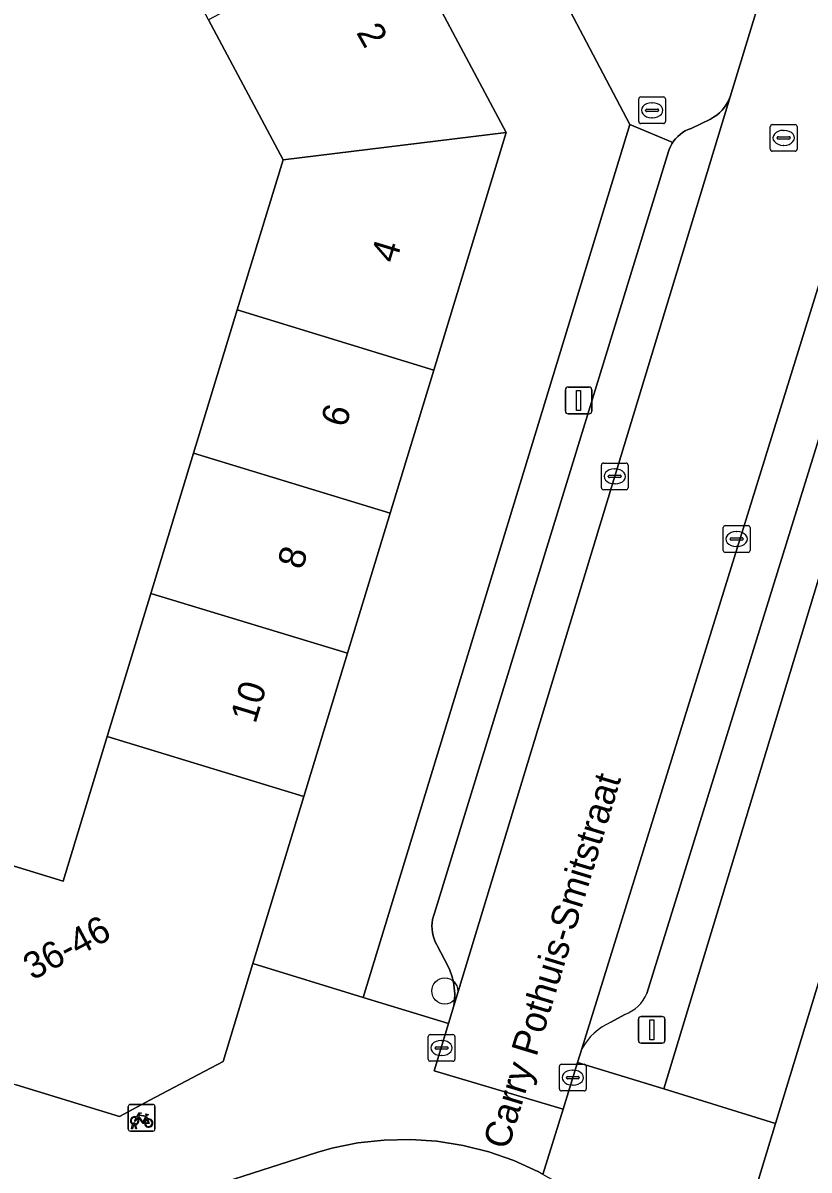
# Model space of a CAD drawing. Extents: x 160304 to 160955, y 383684 to 384161.
# Drawn here: x 160683.55 to 160713, y 383795.43 to 383838.38 of the extents above; entities that cross this region are included whole.
import ezdxf

# ---------------------------------------------------------------- set-up
doc = ezdxf.new("R2010")
doc.units = 0
for name, color, linetype in [('IMGEO_Boom', 7, 'Continuous'), ('IMGEO_Brandkraan', 7, 'Continuous'), ('IMGEO_Erf', 7, 'Continuous'), ('IMGEO_Fietsenrek', 7, 'Continuous'), ('IMGEO_Kolk', 7, 'Continuous'), ('IMGEO_Lichtmast', 7, 'Continuous'), ('IMGEO_Openbare_ruimte_label', 7, 'Continuous'), ('IMGEO_Pand', 7, 'Continuous'), ('IMGEO_Pand_nummerreeks', 7, 'Continuous'), ('IMGEO_Parkeervlak_open', 7, 'Continuous'), ('IMGEO_Rijbaan_lokaal_open', 7, 'Continuous'), ('IMGEO_Rioolput', 7, 'Continuous'), ('IMGEO_Voetpad_open', 7, 'Continuous')]:
    doc.layers.add(name, color=color, linetype=linetype)

msp = doc.modelspace()

# ---------------------------------------------------------------- linework, layer by layer
at = {"layer": 'IMGEO_Boom'}
msp.add_circle((160699.356, 383802.137), 0.489, dxfattribs=at)
at = {"layer": 'IMGEO_Brandkraan'}
for p, q in [((160706.695, 383835.615), (160707.547, 383835.615)), ((160706.62, 383834.689), (160706.62, 383835.541)), ((160707.108, 383835.395), (160707.133, 383835.395)), ((160707.621, 383835.541), (160707.621, 383834.689)), ((160706.879, 383835.109), (160706.879, 383835.121)), ((160707.317, 383835.072), (160706.919, 383835.072)), ((160706.922, 383835.158), (160707.32, 383835.158)), ((160707.131, 383834.835), (160707.106, 383834.835)), ((160707.363, 383835.121), (160707.363, 383835.109)), ((160707.547, 383834.615), (160706.695, 383834.615))]:
    msp.add_line(p, q, dxfattribs=at)
for points in [[(160706.695, 383835.615), (160707.547, 383835.615)], [(160706.62, 383834.689), (160706.62, 383835.541)], [(160707.621, 383835.541), (160707.621, 383834.689)], [(160707.547, 383834.615), (160706.695, 383834.615)]]:
    msp.add_lwpolyline(points, dxfattribs=at)
for centre, radius, start, end in [((160706.697, 383835.539), 0.0765, 91.552, 178.448), ((160706.697, 383835.539), 0.0765, 91.552, 178.448), ((160707.545, 383835.539), 0.0765, 1.552, 88.448), ((160707.545, 383835.539), 0.0765, 1.552, 88.448), ((160706.919, 383835.118), 0.0403, 85.8775, 175.7526), ((160706.916, 383835.108), 0.0366, 178.938, 274.7102), ((160707.32, 383835.115), 0.043, 264.8664, 352.4533), ((160707.324, 383835.12), 0.0386, 1.7309, 96.639), ((160706.697, 383834.691), 0.0765, 181.552, 268.448), ((160706.697, 383834.691), 0.0765, 181.552, 268.448), ((160707.545, 383834.691), 0.0765, 271.552, 358.448), ((160707.545, 383834.691), 0.0765, 271.552, 358.448)]:
    msp.add_arc(centre, radius, start, end, dxfattribs=at)
for centre, major_axis, ratio, start_param, end_param in [((160707.107, 383835.115), (-0.387, 0.002), 0.722429, 4.712389, 7.853982), ((160707.132, 383835.115), (-0.39, 0.002), 0.717154, 1.570796, 4.712389)]:
    msp.add_ellipse(centre, major_axis=major_axis, ratio=ratio, start_param=start_param, end_param=end_param, dxfattribs=at)
at = {"layer": 'IMGEO_Erf'}
for points in [[(160706.29, 383834.575), (160698.822, 383848.768), (160696.833, 383850.07), (160689.542, 383863.958), (160687.096, 383862.66), (160686.663, 383862.43), (160689.481, 383857.138), (160692.156, 383852.115), (160694.833, 383847.089), (160697.446, 383842.182), (160701.657, 383834.275), (160698.945, 383825.386), (160697.309, 383820.026), (160695.709, 383814.78), (160694.073, 383809.418), (160692.164, 383803.164), (160696.3, 383801.889)], [(160734.168, 383835.135), (160739.273, 383837.851), (160744.418, 383840.589), (160742.884, 383843.475), (160733.308, 383838.386), (160731.697, 383838.95), (160717.579, 383831.466), (160707.563, 383798.475), (160711.75, 383797.173), (160714.27, 383805.428), (160715.618, 383809.843), (160716.966, 383814.258), (160718.314, 383818.674), (160721.24, 383828.255), (160729.062, 383832.418)]]:
    msp.add_lwpolyline(points, close=True, dxfattribs=at)
msp.add_lwpolyline([(160679.665, 383807.898), (160685.059, 383806.252), (160686.712, 383811.669), (160688.346, 383817.026), (160689.947, 383822.272), (160691.583, 383827.636), (160693.298, 383833.257), (160690.506, 383838.5), (160687.891, 383843.41), (160685.222, 383848.423), (160682.541, 383853.456)], dxfattribs=at)
at = {"layer": 'IMGEO_Fietsenrek'}
for p, q in [((160687.571, 383797.891), (160688.412, 383797.891)), ((160688.412, 383797.891), (160687.571, 383797.891)), ((160688.496, 383797.816), (160688.496, 383796.975)), ((160688.496, 383796.975), (160688.496, 383797.816)), ((160687.496, 383796.966), (160687.496, 383797.807)), ((160687.496, 383797.807), (160687.496, 383796.966)), ((160688.183, 383797.44), (160688.219, 383797.345)), ((160687.623, 383796.975), (160687.662, 383797.135)), ((160687.657, 383796.975), (160687.623, 383796.975)), ((160687.692, 383797.123), (160687.657, 383796.975)), ((160687.734, 383797.147), (160687.733, 383797.151)), ((160687.775, 383796.975), (160687.741, 383797.117)), ((160687.765, 383797.158), (160687.766, 383797.151)), ((160687.773, 383797.121), (160687.808, 383796.975)), ((160687.808, 383796.975), (160687.775, 383796.975)), ((160688.421, 383796.891), (160687.58, 383796.891)), ((160687.58, 383796.891), (160688.421, 383796.891))]:
    msp.add_line(p, q, dxfattribs=at)
for points in [[(160687.83, 383797.365), (160687.778, 383797.275), (160687.738, 383797.25), (160687.739, 383797.297), (160687.794, 383797.391)], [(160687.809, 383797.417), (160687.904, 383797.581), (160687.99, 383797.567), (160687.992, 383797.558), (160687.936, 383797.547), (160687.909, 383797.502), (160688.165, 383797.461)], [(160688.105, 383797.173), (160688.055, 383797.173), (160687.864, 383797.424), (160687.845, 383797.392)], [(160688.152, 383797.436), (160687.895, 383797.477), (160687.878, 383797.448), (160688.045, 383797.228), (160688.152, 383797.436)], [(160688.2, 383797.338), (160688.17, 383797.415), (160688.061, 383797.197), (160688.104, 383797.197)], [(160688.165, 383797.461), (160688.19, 383797.51), (160688.184, 383797.514), (160688.161, 383797.518), (160688.149, 383797.525), (160688.148, 383797.528), (160688.15, 383797.533), (160688.245, 383797.518), (160688.247, 383797.508), (160688.237, 383797.495), (160688.225, 383797.489), (160688.211, 383797.495), (160688.183, 383797.44)], [(160688.134, 383797.197), (160688.254, 383797.196), (160688.21, 383797.31)], [(160688.23, 383797.317), (160688.285, 383797.172), (160688.135, 383797.172)]]:
    msp.add_lwpolyline(points, dxfattribs=at)
for centre, radius, start, end in [((160687.574, 383797.813), 0.0779, 92.4484, 184.2845), ((160687.574, 383797.813), 0.0779, 92.4484, 184.2845), ((160688.418, 383797.813), 0.0779, 2.4484, 94.2845), ((160688.418, 383797.813), 0.0779, 2.4484, 94.2845), ((160687.736, 383797.276), 0.159, 62.6766, 242.1369), ((160687.736, 383797.276), 0.129, 63.3192, 238.903), ((160687.736, 383797.276), 0.159, 283.5766, 46.6042), ((160687.574, 383796.969), 0.0779, 182.4484, 274.2845), ((160687.574, 383796.969), 0.0779, 182.4484, 274.2845), ((160687.716, 383797.147), 0.0499, 12.8025, 158.6934), ((160687.736, 383797.276), 0.159, 253.9967, 271.7867), ((160687.716, 383797.147), 0.0174, 12.8025, 163.4502), ((160687.736, 383797.276), 0.129, 253.415, 269.0204), ((160687.736, 383797.276), 0.129, 283.6043, 43.4302), ((160688.263, 383797.192), 0.159, 113.3408, 178.3217), ((160688.263, 383797.192), 0.159, 187.0065, 105.7708), ((160688.263, 383797.192), 0.129, 113.923, 177.9556), ((160688.263, 383797.192), 0.129, 188.6715, 104.5883), ((160688.418, 383796.969), 0.0779, 272.4484, 4.2845), ((160688.418, 383796.969), 0.0779, 272.4484, 4.2845)]:
    msp.add_arc(centre, radius, start, end, dxfattribs=at)
at = {"layer": 'IMGEO_Kolk'}
for p, q in [((160705.297, 383821.905), (160706.149, 383821.905)), ((160705.222, 383820.979), (160705.222, 383821.831)), ((160705.524, 383821.448), (160705.922, 383821.448)), ((160705.71, 383821.685), (160705.735, 383821.685)), ((160706.223, 383821.831), (160706.223, 383820.979)), ((160705.481, 383821.399), (160705.481, 383821.411)), ((160705.919, 383821.362), (160705.521, 383821.362)), ((160705.733, 383821.125), (160705.708, 383821.125)), ((160705.965, 383821.411), (160705.965, 383821.399)), ((160706.149, 383820.905), (160705.297, 383820.905)), ((160709.788, 383818.634), (160709.788, 383819.486)), ((160709.863, 383819.56), (160710.715, 383819.56)), ((160710.276, 383819.34), (160710.301, 383819.34)), ((160710.789, 383819.486), (160710.789, 383818.634)), ((160710.047, 383819.054), (160710.047, 383819.066)), ((160710.485, 383819.017), (160710.087, 383819.017)), ((160710.09, 383819.103), (160710.488, 383819.103)), ((160710.531, 383819.066), (160710.531, 383819.054)), ((160710.715, 383818.56), (160709.863, 383818.56)), ((160710.299, 383818.78), (160710.274, 383818.78)), ((160698.733, 383799.578), (160698.733, 383800.43)), ((160698.808, 383800.504), (160699.66, 383800.504)), ((160699.734, 383800.43), (160699.734, 383799.578)), ((160698.992, 383799.998), (160698.992, 383800.01)), ((160699.43, 383799.961), (160699.032, 383799.961)), ((160699.035, 383800.047), (160699.433, 383800.047)), ((160699.221, 383800.284), (160699.246, 383800.284)), ((160699.476, 383800.01), (160699.476, 383799.998)), ((160699.244, 383799.724), (160699.219, 383799.724)), ((160699.66, 383799.504), (160698.808, 383799.504)), ((160703.65, 383798.467), (160703.65, 383799.319)), ((160703.725, 383799.393), (160704.577, 383799.393)), ((160704.138, 383799.173), (160704.163, 383799.173)), ((160704.651, 383799.319), (160704.651, 383798.467)), ((160703.909, 383798.887), (160703.909, 383798.899)), ((160704.347, 383798.85), (160703.949, 383798.85)), ((160703.952, 383798.936), (160704.35, 383798.936)), ((160704.393, 383798.899), (160704.393, 383798.887)), ((160704.577, 383798.393), (160703.725, 383798.393)), ((160704.161, 383798.613), (160704.136, 383798.613))]:
    msp.add_line(p, q, dxfattribs=at)
for points in [[(160705.297, 383821.905), (160706.149, 383821.905)], [(160705.222, 383820.979), (160705.222, 383821.831)], [(160706.223, 383821.831), (160706.223, 383820.979)], [(160706.149, 383820.905), (160705.297, 383820.905)], [(160709.788, 383818.634), (160709.788, 383819.486)], [(160709.863, 383819.56), (160710.715, 383819.56)], [(160710.789, 383819.486), (160710.789, 383818.634)], [(160710.715, 383818.56), (160709.863, 383818.56)], [(160698.733, 383799.578), (160698.733, 383800.43)], [(160698.808, 383800.504), (160699.66, 383800.504)], [(160699.734, 383800.43), (160699.734, 383799.578)], [(160699.66, 383799.504), (160698.808, 383799.504)], [(160703.65, 383798.467), (160703.65, 383799.319)], [(160703.725, 383799.393), (160704.577, 383799.393)], [(160704.651, 383799.319), (160704.651, 383798.467)], [(160704.577, 383798.393), (160703.725, 383798.393)]]:
    msp.add_lwpolyline(points, dxfattribs=at)
for centre, radius, start, end in [((160705.299, 383821.829), 0.0765, 91.552, 178.448), ((160705.299, 383821.829), 0.0765, 91.552, 178.448), ((160706.147, 383821.829), 0.0765, 1.552, 88.448), ((160706.147, 383821.829), 0.0765, 1.552, 88.448), ((160705.521, 383821.408), 0.0403, 85.8775, 175.7526), ((160705.926, 383821.41), 0.0386, 1.7309, 96.639), ((160705.518, 383821.398), 0.0366, 178.938, 274.7102), ((160705.922, 383821.405), 0.043, 264.8664, 352.4533), ((160705.299, 383820.981), 0.0765, 181.552, 268.448), ((160705.299, 383820.981), 0.0765, 181.552, 268.448), ((160706.147, 383820.981), 0.0765, 271.552, 358.448), ((160706.147, 383820.981), 0.0765, 271.552, 358.448), ((160709.865, 383819.484), 0.0765, 91.552, 178.448), ((160709.865, 383819.484), 0.0765, 91.552, 178.448), ((160710.713, 383819.484), 0.0765, 1.552, 88.448), ((160710.713, 383819.484), 0.0765, 1.552, 88.448), ((160710.087, 383819.063), 0.0403, 85.8775, 175.7526), ((160710.084, 383819.053), 0.0366, 178.938, 274.7102), ((160710.488, 383819.06), 0.043, 264.8664, 352.4533), ((160710.492, 383819.065), 0.0386, 1.7309, 96.639), ((160709.865, 383818.636), 0.0765, 181.552, 268.448), ((160709.865, 383818.636), 0.0765, 181.552, 268.448), ((160710.713, 383818.636), 0.0765, 271.552, 358.448), ((160710.713, 383818.636), 0.0765, 271.552, 358.448), ((160698.81, 383800.428), 0.0765, 91.552, 178.448), ((160698.81, 383800.428), 0.0765, 91.552, 178.448), ((160699.658, 383800.428), 0.0765, 1.552, 88.448), ((160699.658, 383800.428), 0.0765, 1.552, 88.448), ((160699.032, 383800.007), 0.0403, 85.8775, 175.7526), ((160699.029, 383799.997), 0.0366, 178.938, 274.7102), ((160699.433, 383800.004), 0.043, 264.8664, 352.4533), ((160699.437, 383800.009), 0.0386, 1.7309, 96.639), ((160698.81, 383799.58), 0.0765, 181.552, 268.448), ((160698.81, 383799.58), 0.0765, 181.552, 268.448), ((160699.658, 383799.58), 0.0765, 271.552, 358.448), ((160699.658, 383799.58), 0.0765, 271.552, 358.448), ((160703.727, 383799.317), 0.0765, 91.552, 178.448), ((160703.727, 383799.317), 0.0765, 91.552, 178.448), ((160704.575, 383799.317), 0.0765, 1.552, 88.448), ((160704.575, 383799.317), 0.0765, 1.552, 88.448), ((160703.949, 383798.896), 0.0403, 85.8775, 175.7526), ((160703.946, 383798.886), 0.0366, 178.938, 274.7102), ((160704.35, 383798.893), 0.043, 264.8664, 352.4533), ((160704.354, 383798.898), 0.0386, 1.7309, 96.639), ((160703.727, 383798.469), 0.0765, 181.552, 268.448), ((160703.727, 383798.469), 0.0765, 181.552, 268.448), ((160704.575, 383798.469), 0.0765, 271.552, 358.448), ((160704.575, 383798.469), 0.0765, 271.552, 358.448)]:
    msp.add_arc(centre, radius, start, end, dxfattribs=at)
for centre, major_axis, ratio, start_param, end_param in [((160705.709, 383821.405), (-0.387, 0.002), 0.722429, 4.712389, 7.853982), ((160705.734, 383821.405), (-0.39, 0.002), 0.717154, 1.570796, 4.712389), ((160710.275, 383819.06), (-0.387, 0.002), 0.722429, 4.712389, 7.853982), ((160710.3, 383819.06), (-0.39, 0.002), 0.717154, 1.570796, 4.712389), ((160699.22, 383800.004), (-0.387, 0.002), 0.722429, 4.712389, 7.853982), ((160699.245, 383800.004), (-0.39, 0.002), 0.717154, 1.570796, 4.712389), ((160704.137, 383798.893), (-0.387, 0.002), 0.722429, 4.712389, 7.853982), ((160704.162, 383798.893), (-0.39, 0.002), 0.717154, 1.570796, 4.712389)]:
    msp.add_ellipse(centre, major_axis=major_axis, ratio=ratio, start_param=start_param, end_param=end_param, dxfattribs=at)
at = {"layer": 'IMGEO_Lichtmast'}
for p, q in [((160703.875, 383823.849), (160703.875, 383824.649)), ((160703.875, 383824.649), (160703.875, 383823.849)), ((160703.975, 383824.749), (160704.765, 383824.749)), ((160704.765, 383824.749), (160703.975, 383824.749)), ((160704.865, 383824.649), (160704.865, 383823.849)), ((160704.865, 383823.849), (160704.865, 383824.649)), ((160704.765, 383823.749), (160703.975, 383823.749)), ((160703.975, 383823.749), (160704.765, 383823.749)), ((160706.61, 383800.283), (160706.61, 383801.083)), ((160706.61, 383801.083), (160706.61, 383800.283)), ((160706.71, 383801.183), (160707.5, 383801.183)), ((160707.5, 383801.183), (160706.71, 383801.183)), ((160707.6, 383801.083), (160707.6, 383800.283)), ((160707.6, 383800.283), (160707.6, 383801.083)), ((160707.5, 383800.183), (160706.71, 383800.183)), ((160706.71, 383800.183), (160707.5, 383800.183))]:
    msp.add_line(p, q, dxfattribs=at)
for points in [[(160704.295, 383824.624), (160704.445, 383824.624), (160704.445, 383823.874), (160704.295, 383823.874), (160704.295, 383824.624)], [(160707.03, 383801.058), (160707.18, 383801.058), (160707.18, 383800.308), (160707.03, 383800.308), (160707.03, 383801.058)]]:
    msp.add_lwpolyline(points, dxfattribs=at)
for centre, start, end in [((160703.975, 383824.649), 90, 180), ((160703.975, 383824.649), 90, 180), ((160704.765, 383824.649), 0, 90), ((160704.765, 383824.649), 360, 90), ((160703.975, 383823.849), 180, 270), ((160703.975, 383823.849), 180, 270), ((160704.765, 383823.849), 270, 0), ((160704.765, 383823.849), 270, 0), ((160706.71, 383801.083), 90, 180), ((160706.71, 383801.083), 90, 180), ((160707.5, 383801.083), 0, 90), ((160707.5, 383801.083), 360, 90), ((160706.71, 383800.283), 180, 270), ((160706.71, 383800.283), 180, 270), ((160707.5, 383800.283), 270, 0), ((160707.5, 383800.283), 270, 0)]:
    msp.add_arc(centre, 0.1, start, end, dxfattribs=at)
at = {"layer": 'IMGEO_Pand'}
for points in [[(160701.657, 383834.275), (160697.446, 383842.182), (160690.506, 383838.5), (160693.298, 383833.257)], [(160698.945, 383825.386), (160701.657, 383834.275), (160693.298, 383833.257), (160691.583, 383827.636)], [(160698.945, 383825.386), (160691.583, 383827.636), (160689.947, 383822.272), (160697.309, 383820.026)], [(160688.346, 383817.026), (160695.709, 383814.78), (160697.309, 383820.026), (160689.947, 383822.272)], [(160686.712, 383811.669), (160694.073, 383809.418), (160695.709, 383814.78), (160688.346, 383817.026)], [(160694.073, 383809.418), (160686.712, 383811.669), (160685.059, 383806.252), (160679.665, 383807.898), (160677.387, 383800.427), (160683.302, 383798.622), (160687.175, 383797.44), (160688.311, 383798.045), (160689.891, 383798.887), (160691.047, 383799.502), (160692.164, 383803.164)], [(160719.497, 383795.67), (160721.777, 383803.136), (160714.27, 383805.428), (160711.75, 383797.173), (160710.644, 383793.552), (160711.282, 383792.356), (160712.128, 383790.767), (160712.738, 383789.619), (160716.717, 383788.404), (160723.048, 383786.471), (160725.313, 383793.894)]]:
    msp.add_lwpolyline(points, close=True, dxfattribs=at)
at = {"layer": 'IMGEO_Parkeervlak_open'}
msp.add_lwpolyline([(160710.047, 383835.62), (160710.036, 383835.592), (160709.979, 383835.465), (160709.911, 383835.344), (160709.833, 383835.229), (160709.744, 383835.122), (160709.646, 383835.023), (160709.54, 383834.933), (160709.426, 383834.853), (160709.306, 383834.784), (160708.582, 383834.429), (160708.472, 383834.388), (160708.366, 383834.338), (160708.265, 383834.278), (160708.17, 383834.21), (160708.082, 383834.133), (160708, 383834.049), (160707.927, 383833.957), (160707.894, 383833.909), (160707.861, 383833.86), (160707.805, 383833.757), (160707.759, 383833.65), (160707.73, 383833.567), (160698.968, 383805.05), (160698.928, 383804.934), (160698.899, 383804.815), (160698.881, 383804.694), (160698.873, 383804.572), (160698.877, 383804.45), (160698.891, 383804.328), (160698.916, 383804.208), (160698.952, 383804.091), (160698.998, 383803.978), (160699.054, 383803.869), (160699.069, 383803.844), (160699.487, 383803.057), (160699.548, 383802.915), (160699.622, 383802.7), (160699.677, 383802.48), (160699.712, 383802.255), (160699.726, 383802.029), (160699.72, 383801.802), (160699.694, 383801.576)], close=True, dxfattribs=at)
for points in [[(160715.178, 383834.409), (160704.49, 383799.969)], [(160706.926, 383802.048), (160715.92, 383831.029)], [(160705.579, 383800.97), (160706.1, 383801.262)]]:
    msp.add_lwpolyline(points, dxfattribs=at)
for centre, radius, start, end in [((160705.634, 383802.579), 1.397, 289.4871, 337.6701), ((160706.514, 383798.86), 2.308, 113.8967, 151.2813)]:
    msp.add_arc(centre, radius, start, end, dxfattribs=at)
at = {"layer": 'IMGEO_Rijbaan_lokaal_open'}
for points in [[(160711.901, 383841.718), (160710.047, 383835.62), (160699.694, 383801.576), (160699.495, 383800.921), (160698.957, 383799.151), (160703.79, 383797.713), (160704.331, 383799.455), (160704.49, 383799.969), (160715.178, 383834.409)], [(160707.183, 383791.418), (160706.617, 383792.231), (160705.98, 383792.99), (160705.279, 383793.69), (160704.517, 383794.323), (160703.702, 383794.887), (160703.03, 383795.267), (160702.84, 383795.375), (160701.938, 383795.784), (160701.002, 383796.111), (160700.042, 383796.353), (160699.063, 383796.509), (160698.075, 383796.576), (160697.084, 383796.555), (160696.1, 383796.445), (160695.129, 383796.248), (160694.567, 383796.092), (160684.538, 383792.874), (160684.293, 383792.805), (160683.73, 383792.686), (160683.158, 383792.617)]]:
    msp.add_lwpolyline(points, dxfattribs=at)
at = {"layer": 'IMGEO_Rioolput'}
for p, q in [((160711.55, 383833.654), (160711.55, 383834.506)), ((160711.625, 383834.58), (160712.477, 383834.58)), ((160712.038, 383834.36), (160712.063, 383834.36)), ((160712.551, 383834.506), (160712.551, 383833.654)), ((160711.809, 383834.074), (160711.809, 383834.086)), ((160712.247, 383834.037), (160711.849, 383834.037)), ((160711.852, 383834.123), (160712.25, 383834.123)), ((160712.293, 383834.086), (160712.293, 383834.074)), ((160712.477, 383833.58), (160711.625, 383833.58)), ((160712.061, 383833.8), (160712.036, 383833.8))]:
    msp.add_line(p, q, dxfattribs=at)
for points in [[(160711.55, 383833.654), (160711.55, 383834.506)], [(160711.625, 383834.58), (160712.477, 383834.58)], [(160712.551, 383834.506), (160712.551, 383833.654)], [(160712.477, 383833.58), (160711.625, 383833.58)]]:
    msp.add_lwpolyline(points, dxfattribs=at)
for centre, radius, start, end in [((160711.627, 383834.504), 0.0765, 91.552, 178.448), ((160711.627, 383834.504), 0.0765, 91.552, 178.448), ((160712.475, 383834.504), 0.0765, 1.552, 88.448), ((160712.475, 383834.504), 0.0765, 1.552, 88.448), ((160711.849, 383834.083), 0.0403, 85.8775, 175.7526), ((160711.846, 383834.073), 0.0366, 178.938, 274.7102), ((160712.25, 383834.08), 0.043, 264.8664, 352.4533), ((160712.254, 383834.085), 0.0386, 1.7309, 96.639), ((160711.627, 383833.656), 0.0765, 181.552, 268.448), ((160711.627, 383833.656), 0.0765, 181.552, 268.448), ((160712.475, 383833.656), 0.0765, 271.552, 358.448), ((160712.475, 383833.656), 0.0765, 271.552, 358.448)]:
    msp.add_arc(centre, radius, start, end, dxfattribs=at)
for centre, major_axis, ratio, start_param, end_param in [((160712.037, 383834.08), (-0.387, 0.002), 0.722429, 4.712389, 7.853982), ((160712.062, 383834.08), (-0.39, 0.002), 0.717154, 1.570796, 4.712389)]:
    msp.add_ellipse(centre, major_axis=major_axis, ratio=ratio, start_param=start_param, end_param=end_param, dxfattribs=at)
at = {"layer": 'IMGEO_Voetpad_open'}
for points in [[(160698.822, 383848.768), (160706.29, 383834.575), (160707.894, 383833.909), (160707.927, 383833.957), (160708, 383834.049), (160708.082, 383834.133), (160708.17, 383834.21), (160708.265, 383834.278), (160708.366, 383834.338), (160708.472, 383834.388), (160708.582, 383834.429), (160709.306, 383834.784), (160709.426, 383834.853), (160709.54, 383834.933), (160709.646, 383835.023), (160709.744, 383835.122), (160709.833, 383835.229), (160709.911, 383835.344), (160709.979, 383835.465), (160710.036, 383835.592), (160710.047, 383835.62), (160711.901, 383841.718)], [(160704.49, 383799.969), (160704.331, 383799.455), (160707.563, 383798.475), (160717.579, 383831.466)], [(160715.92, 383831.029), (160706.926, 383802.048)], [(160703.03, 383795.267), (160703.79, 383797.713), (160698.957, 383799.151), (160699.495, 383800.921), (160696.3, 383801.889), (160692.164, 383803.164), (160691.047, 383799.502), (160689.891, 383798.887), (160688.311, 383798.045), (160687.175, 383797.44), (160683.302, 383798.622)], [(160706.1, 383801.262), (160705.579, 383800.97)], [(160710.644, 383793.552), (160711.75, 383797.173), (160707.563, 383798.475), (160704.331, 383799.455), (160703.79, 383797.713), (160703.03, 383795.267)], [(160684.538, 383792.874), (160694.567, 383796.092), (160695.129, 383796.248), (160696.1, 383796.445), (160697.084, 383796.555), (160698.075, 383796.576), (160699.063, 383796.509), (160700.042, 383796.353), (160701.002, 383796.111), (160701.938, 383795.784), (160702.84, 383795.375)]]:
    msp.add_lwpolyline(points, dxfattribs=at)
msp.add_lwpolyline([(160699.548, 383802.915), (160699.487, 383803.057), (160699.069, 383803.844), (160699.054, 383803.869), (160698.998, 383803.978), (160698.952, 383804.091), (160698.916, 383804.208), (160698.891, 383804.328), (160698.877, 383804.45), (160698.873, 383804.572), (160698.881, 383804.694), (160698.899, 383804.815), (160698.928, 383804.934), (160698.968, 383805.05), (160707.73, 383833.567), (160707.759, 383833.65), (160707.805, 383833.757), (160707.861, 383833.86), (160707.894, 383833.909), (160706.29, 383834.575), (160696.3, 383801.889), (160699.495, 383800.921), (160699.694, 383801.576), (160699.72, 383801.802), (160699.726, 383802.029), (160699.712, 383802.255), (160699.677, 383802.48), (160699.622, 383802.7)], close=True, dxfattribs=at)
for centre, radius, start, end in [((160705.634, 383802.579), 1.397, 289.4871, 337.6701), ((160706.514, 383798.86), 2.308, 113.8967, 151.2813)]:
    msp.add_arc(centre, radius, start, end, dxfattribs=at)

# ---------------------------------------------------------------- texts
at = {"layer": 'IMGEO_Openbare_ruimte_label'}
msp.add_text('Carry Pothuis-Smitstraat', height=1, rotation=73.0868, dxfattribs=at).set_placement((160701.727, 383796.161))
at = {"layer": 'IMGEO_Pand_nummerreeks'}
for s, rotation, p in [('2', 299.3977, (160696.021, 383838.027)), ('4', 73.0339, (160697.517, 383829.348)), ('6', 73.0325, (160695.642, 383823.197)), ('8', 73.0325, (160694.019, 383817.878)), ('10', 73.0325, (160692.26, 383812.115)), ('36-46', 28.052, (160683.909, 383802.52))]:
    msp.add_text(s, height=1, rotation=rotation, dxfattribs=at).set_placement(p)

doc.saveas('drawing.dxf')
